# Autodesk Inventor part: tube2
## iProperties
Created: 2008-12
Part Number: tube2
Document SubType Name: Modeling
Designer: LCM
Author: LCM
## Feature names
1. Balayage1
2. Balayage2
3. Extrusion1
4. Congé1 [Fillet]
5. Balayage3
6. Extrusion2
7. Balayage4
8. Extrusion3
9. Balayage5
10. Extrusion5
11. Congé2 [Fillet]
12. Balayage6
13. Extrusion7
14. Révolution1 [Revolution]
15. Miroir2 [Mirror]
